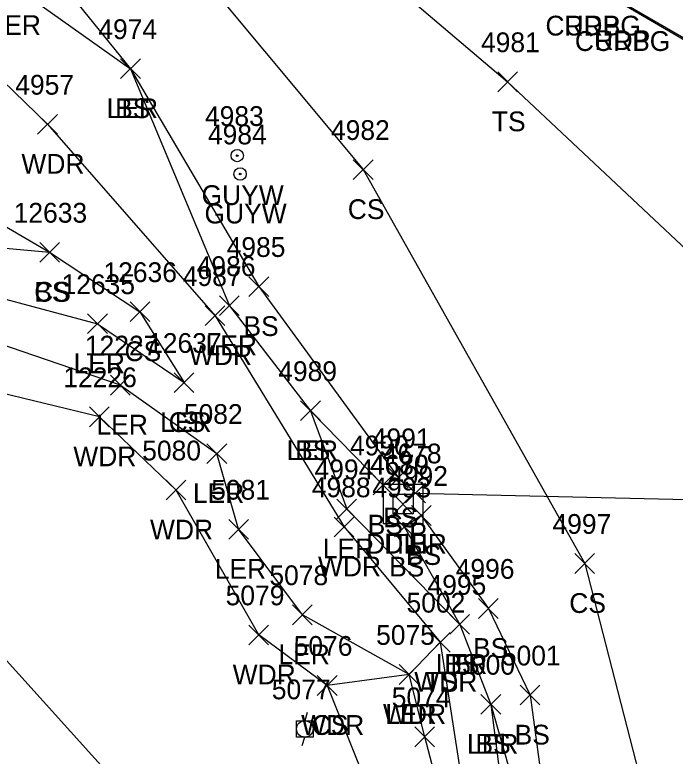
# Model space of a CAD drawing. Extents: x 1462089 to 1464015, y 730534 to 736144.
# Drawn here: x 1462520.7 to 1462587.6, y 731574.8 to 731649.8 of the extents above; entities that cross this region are included whole.
import ezdxf

# ---------------------------------------------------------------- set-up
doc = ezdxf.new("R2010")
doc.units = 0
for name, color, linetype in [('D_A', 7, 'Continuous'), ('D_I', 7, 'Continuous'), ('D_TIC', 7, 'Continuous'), ('DCP', 7, 'Continuous'), ('DS', 7, 'Continuous'), ('L_A', 7, 'Continuous'), ('L_I', 7, 'Continuous'), ('L_TIC', 7, 'Continuous'), ('LARO', 7, 'Continuous'), ('LAWA', 7, 'Continuous'), ('LELB', 7, 'Continuous'), ('P_A', 7, 'Continuous'), ('PET', 7, 'Continuous'), ('R_A', 7, 'Continuous'), ('RC', 7, 'Continuous'), ('U_A', 7, 'Continuous'), ('U_I', 7, 'Continuous'), ('UP', 7, 'Continuous'), ('UPGW', 7, 'Continuous')]:
    doc.layers.add(name, color=color, linetype=linetype)

msp = doc.modelspace()

# ---------------------------------------------------------------- linework, layer by layer
at = {"layer": 'D_TIC'}
for points in [[(1462560.299, 731600.383), (1462562.299, 731602.383)], [(1462562.299, 731600.383), (1462560.299, 731602.383)], [(1462559.037, 731599.257), (1462561.037, 731601.257)], [(1462561.037, 731599.257), (1462559.037, 731601.257)]]:
    msp.add_lwpolyline(points, dxfattribs=at)
at = {"layer": 'DCP'}
msp.add_lwpolyline([(1462561.299, 731601.383), (1462626.385, 731599.866)], dxfattribs=at)
at = {"layer": 'DS'}
for p, q in [((1462558.056, 731602.265), (1462562.056, 731602.265)), ((1462558.056, 731598.265), (1462558.067, 731602.265)), ((1462562.056, 731602.265), (1462562.056, 731598.265)), ((1462559.056, 731601.265), (1462561.056, 731601.265)), ((1462559.056, 731599.265), (1462559.056, 731601.265)), ((1462561.056, 731601.265), (1462561.056, 731599.265)), ((1462560.059, 731600.275), (1462560.059, 731600.275)), ((1462561.056, 731599.265), (1462559.056, 731599.265)), ((1462562.056, 731598.265), (1462558.056, 731598.265)), ((1462560.556, 731598.265), (1462561.056, 731598.265))]:
    msp.add_line(p, q, dxfattribs=at)
at = {"layer": 'L_TIC'}
for points in [[(1462531.459, 731643.31), (1462533.459, 731645.31)], [(1462533.459, 731643.31), (1462531.459, 731645.31)], [(1462531.459, 731643.31), (1462533.459, 731645.31)], [(1462533.459, 731643.31), (1462531.459, 731645.31)], [(1462569.627, 731641.981), (1462571.627, 731643.981)], [(1462571.627, 731641.981), (1462569.627, 731643.981)], [(1462523.054, 731637.685), (1462525.054, 731639.685)], [(1462525.054, 731637.685), (1462523.054, 731639.685)], [(1462555.009, 731633.101), (1462557.009, 731635.101)], [(1462557.009, 731633.101), (1462555.009, 731635.101)], [(1462523.269, 731624.736), (1462525.269, 731626.736)], [(1462525.269, 731624.736), (1462523.269, 731626.736)], [(1462523.269, 731624.736), (1462525.269, 731626.736)], [(1462525.269, 731624.736), (1462523.269, 731626.736)], [(1462544.45, 731621.268), (1462546.45, 731623.268)], [(1462546.45, 731621.268), (1462544.45, 731623.268)], [(1462541.472, 731619.329), (1462543.472, 731621.329)], [(1462543.472, 731619.329), (1462541.472, 731621.329)], [(1462532.413, 731618.725), (1462534.413, 731620.725)], [(1462534.413, 731618.725), (1462532.413, 731620.725)], [(1462540.013, 731618.326), (1462542.013, 731620.326)], [(1462542.013, 731618.326), (1462540.013, 731620.326)], [(1462528.113, 731617.507), (1462530.113, 731619.507)], [(1462530.113, 731617.507), (1462528.113, 731619.507)], [(1462530.429, 731611.297), (1462532.429, 731613.297)], [(1462532.429, 731611.297), (1462530.429, 731613.297)], [(1462536.875, 731611.559), (1462538.875, 731613.559)], [(1462538.875, 731611.559), (1462536.875, 731613.559)], [(1462536.875, 731611.559), (1462538.875, 731613.559)], [(1462538.875, 731611.559), (1462536.875, 731613.559)], [(1462549.678, 731608.71), (1462551.678, 731610.71)], [(1462551.678, 731608.71), (1462549.678, 731610.71)], [(1462549.678, 731608.71), (1462551.678, 731610.71)], [(1462551.678, 731608.71), (1462549.678, 731610.71)], [(1462528.306, 731608.09), (1462530.306, 731610.09)], [(1462530.306, 731608.09), (1462528.306, 731610.09)], [(1462540.194, 731604.376), (1462542.194, 731606.376)], [(1462542.194, 731604.376), (1462540.194, 731606.376)], [(1462558.575, 731601.916), (1462560.575, 731603.916)], [(1462560.575, 731601.916), (1462558.575, 731603.916)], [(1462558.575, 731601.916), (1462560.575, 731603.916)], [(1462560.575, 731601.916), (1462558.575, 731603.916)], [(1462557.02, 731601.19), (1462559.02, 731603.19)], [(1462559.02, 731601.19), (1462557.02, 731603.19)], [(1462536.068, 731600.683), (1462538.068, 731602.683)], [(1462538.068, 731600.683), (1462536.068, 731602.683)], [(1462553.342, 731598.778), (1462555.342, 731600.778)], [(1462555.342, 731598.778), (1462553.342, 731600.778)], [(1462560.893, 731598.11), (1462562.893, 731600.11)], [(1462562.893, 731598.11), (1462560.893, 731600.11)], [(1462560.893, 731598.11), (1462562.893, 731600.11)], [(1462562.893, 731598.11), (1462560.893, 731600.11)], [(1462542.397, 731596.715), (1462544.397, 731598.715)], [(1462544.397, 731596.715), (1462542.397, 731598.715)], [(1462553.07, 731596.956), (1462555.07, 731598.956)], [(1462555.07, 731596.956), (1462553.07, 731598.956)], [(1462559.194, 731596.941), (1462561.194, 731598.941)], [(1462561.194, 731596.941), (1462559.194, 731598.941)], [(1462577.427, 731593.254), (1462579.427, 731595.254)], [(1462579.427, 731593.254), (1462577.427, 731595.254)], [(1462548.852, 731588.064), (1462550.852, 731590.064)], [(1462550.852, 731588.064), (1462548.852, 731590.064)], [(1462567.687, 731588.707), (1462569.687, 731590.707)], [(1462569.687, 731588.707), (1462567.687, 731590.707)], [(1462564.778, 731587.089), (1462566.778, 731589.089)], [(1462566.778, 731587.089), (1462564.778, 731589.089)], [(1462564.778, 731587.089), (1462566.778, 731589.089)], [(1462566.778, 731587.089), (1462564.778, 731589.089)], [(1462544.438, 731586.026), (1462546.438, 731588.026)], [(1462546.438, 731586.026), (1462544.438, 731588.026)], [(1462562.813, 731585.287), (1462564.813, 731587.287)], [(1462564.813, 731585.287), (1462562.813, 731587.287)], [(1462562.813, 731585.287), (1462564.813, 731587.287)], [(1462564.813, 731585.287), (1462562.813, 731587.287)], [(1462559.655, 731582.026), (1462561.655, 731584.026)], [(1462561.655, 731582.026), (1462559.655, 731584.026)], [(1462559.655, 731582.026), (1462561.655, 731584.026)], [(1462561.655, 731582.026), (1462559.655, 731584.026)], [(1462551.367, 731580.915), (1462553.367, 731582.915)], [(1462553.367, 731580.915), (1462551.367, 731582.915)], [(1462551.367, 731580.915), (1462553.367, 731582.915)], [(1462553.367, 731580.915), (1462551.367, 731582.915)], [(1462571.894, 731579.941), (1462573.894, 731581.941)], [(1462573.894, 731579.941), (1462571.894, 731581.941)], [(1462567.931, 731579.005), (1462569.931, 731581.005)], [(1462569.931, 731579.005), (1462567.931, 731581.005)], [(1462567.931, 731579.005), (1462569.931, 731581.005)], [(1462569.931, 731579.005), (1462567.931, 731581.005)], [(1462561.237, 731575.714), (1462563.237, 731577.714)], [(1462563.237, 731575.714), (1462561.237, 731577.714)]]:
    msp.add_lwpolyline(points, dxfattribs=at)
at = {"layer": 'LARO'}
for points in [[(1462346.484, 731772.245), (1462377.204, 731754.639), (1462387.4, 731743.258), (1462405.336, 731739.989), (1462422.595, 731728.101), (1462430.525, 731721.568), (1462436.62, 731722.191), (1462456.917, 731710.315), (1462466.227, 731695.84), (1462493.617, 731678.674), (1462505.155, 731669.137), (1462520.606, 731652.722), (1462532.459, 731644.31), (1462542.472, 731620.329), (1462550.678, 731609.71), (1462554.342, 731599.778), (1462565.778, 731588.089), (1462568.931, 731580.005), (1462570.713, 731566.112), (1462578.995, 731548.691), (1462583.025, 731541.222), (1462579.132, 731509.105)], [(1462531.429, 731612.297), (1462506.669, 731620.754), (1462488.794, 731629.315), (1462466.858, 731635.352), (1462444.766, 731644.234), (1462441.056, 731648.619), (1462444.441, 731652.191), (1462428.639, 731671.832), (1462423.479, 731679.306)], [(1462509.927, 731627.255), (1462515.984, 731622.019), (1462529.113, 731618.507), (1462537.875, 731612.559)], [(1462531.429, 731612.297), (1462541.194, 731605.376)], [(1462573.728, 731494.742), (1462573.697, 731512.314), (1462577.788, 731520.965), (1462576.572, 731538.535), (1462568.613, 731559.706), (1462565.96, 731562.601), (1462562.237, 731576.714), (1462560.655, 731583.026), (1462549.852, 731589.064), (1462543.397, 731597.715), (1462541.194, 731605.376)]]:
    msp.add_lwpolyline(points, dxfattribs=at)
at = {"layer": 'LAWA'}
for points in [[(1462353.486, 731759.008), (1462368.091, 731753.052), (1462369.061, 731740.918), (1462384.402, 731732.963), (1462402.803, 731736.533), (1462419.775, 731723.669), (1462429.629, 731717.395), (1462437.688, 731715.11), (1462449.892, 731706.469), (1462461.801, 731688.892), (1462471.295, 731683.685), (1462488.007, 731676.157), (1462499.088, 731668.041), (1462511.531, 731650.799), (1462524.054, 731638.685), (1462541.013, 731619.326), (1462554.07, 731597.956), (1462563.813, 731586.287), (1462560.655, 731583.026), (1462552.367, 731581.915), (1462545.438, 731587.026), (1462537.068, 731601.683)], [(1462529.306, 731609.09), (1462503.687, 731615.303), (1462482.961, 731621.756), (1462463.284, 731631.864), (1462443.061, 731640.907), (1462419.395, 731655.593), (1462381.114, 731680.146), (1462355.304, 731693.116), (1462311.252, 731715.6), (1462266.509, 731744.615)], [(1462529.306, 731609.09), (1462537.068, 731601.683)]]:
    msp.add_lwpolyline(points, dxfattribs=at)
at = {"layer": 'LELB'}
for points in [[(1462199.973, 731862.797), (1462226.522, 731848.633), (1462244.469, 731839.44), (1462279.961, 731820.277), (1462307.49, 731805.659), (1462330.44, 731793.577), (1462345.388, 731783.622), (1462390.349, 731759.437), (1462428.457, 731739.343), (1462460.592, 731719.83), (1462475.515, 731708.509), (1462501.897, 731689.799), (1462542.27, 731667.043), (1462570.627, 731642.981), (1462603.035, 731612.581), (1462606.866, 731588.462), (1462599.353, 731546.54), (1462591.287, 731500.049)], [(1462501.897, 731689.799), (1462536.038, 731658.093), (1462556.009, 731634.101), (1462578.427, 731594.254), (1462586.04, 731564.762), (1462589.678, 731543.502), (1462586.226, 731501.088), (1462585.38, 731483.091)], [(1462507.864, 731671.1), (1462523.961, 731654.827), (1462532.459, 731644.31), (1462545.45, 731622.268), (1462559.575, 731602.916)], [(1462482.103, 731646.041), (1462492.873, 731646.898), (1462507.297, 731640.119), (1462513.55, 731631.987), (1462524.269, 731625.736), (1462533.413, 731619.725), (1462537.875, 731612.559)], [(1462513.55, 731631.987), (1462514.974, 731626.603), (1462524.269, 731625.736)], [(1462485.976, 731369.759), (1462496.617, 731406.25), (1462504.749, 731449.66), (1462520.791, 731495.659), (1462536.556, 731542.788), (1462536.235, 731566.321), (1462513.747, 731591.256), (1462486.764, 731604.845), (1462473.899, 731602.315), (1462450.444, 731613.383), (1462450.102, 731624.659)], [(1462550.678, 731609.71), (1462558.02, 731602.19), (1462559.575, 731602.916)], [(1462561.893, 731599.11), (1462560.194, 731597.941), (1462565.778, 731588.089)], [(1462561.893, 731599.11), (1462568.687, 731589.707), (1462572.894, 731580.941), (1462574.892, 731566.204), (1462582.199, 731549.938), (1462584.642, 731541.473), (1462582.439, 731502.238), (1462581.625, 731485.919)], [(1462563.813, 731586.287), (1462567.019, 731565.613), (1462565.96, 731562.601), (1462564.718, 731551.054), (1462571.579, 731530.336), (1462567.567, 731501.933), (1462566.111, 731482.199), (1462562.411, 731454.244), (1462553.122, 731413.381), (1462540.13, 731378.267), (1462533.588, 731363.392), (1462525.417, 731358.784)], [(1462552.367, 731581.915), (1462564.718, 731551.054)], [(1462568.931, 731580.005), (1462573.043, 731565.54), (1462578.995, 731548.691)]]:
    msp.add_lwpolyline(points, dxfattribs=at)
at = {"layer": 'PET'}
msp.add_lwpolyline([(1462201.656, 731866.043), (1462245.703, 731842.087), (1462281.75, 731822.984), (1462308.734, 731808.187), (1462347.652, 731787.037), (1462392.209, 731761.837), (1462429.222, 731740.598), (1462448.896, 731730.041), (1462477.729, 731709.286), (1462504.154, 731693.872), (1462543.73, 731671.863), (1462578.876, 731652.667), (1462581.934, 731651.196), (1462611.072, 731634.393), (1462616.428, 731629.037), (1462620.383, 731622.699), (1462623.597, 731614.859), (1462625.47, 731606.659), (1462626.295, 731597.635), (1462624.657, 731584.618)], dxfattribs=at)
at = {"layer": 'RC'}
msp.add_lwpolyline([(1462578.876, 731652.667), (1462581.853, 731651.105), (1462610.886, 731634.194), (1462616.077, 731628.889), (1462620.047, 731622.437), (1462623.426, 731614.745), (1462625.292, 731606.639), (1462626.134, 731597.744), (1462624.33, 731584.747), (1462611.563, 731543.975), (1462595.819, 731494.509), (1462581.283, 731447.508), (1462570.058, 731410.565), (1462558.535, 731373.066), (1462554.642, 731364.371), (1462548.372, 731356.851), (1462540.364, 731351.769), (1462530.201, 731348.551)], dxfattribs=at)
at = {"layer": 'UP'}
for p, q in [((1462550.346, 731579.186), (1462550.096, 731578.353)), ((1462549.263, 731576.686), (1462549.263, 731578.353)), ((1462549.263, 731578.353), (1462550.93, 731578.353)), ((1462550.93, 731578.353), (1462550.93, 731576.686)), ((1462550.096, 731577.519), (1462550.096, 731577.519)), ((1462550.93, 731576.686), (1462549.263, 731576.686)), ((1462549.846, 731575.853), (1462550.096, 731576.686))]:
    msp.add_line(p, q, dxfattribs=at)
msp.add_circle((1462550.096, 731577.519), 0.833, dxfattribs=at)
at = {"layer": 'UPGW'}
for centre, radius in [((1462543.256, 731635.518), 0.625), ((1462543.256, 731635.518), 0.0833), ((1462543.554, 731633.656), 0.625), ((1462543.554, 731633.656), 0.0833)]:
    msp.add_circle(centre, radius, dxfattribs=at)

# ---------------------------------------------------------------- texts
at = {"layer": 'D_A'}
for s, p in [('P', (1462560.677, 731596.383)), ('DITHR', (1462556.303, 731595.244)), ('DIB', (1462558.139, 731595.257))]:
    msp.add_text(s, height=2, dxfattribs=at).set_placement(p)
at = {"layer": 'D_I'}
for s, p in [('4678', (1462557.992, 731604.383)), ('4680', (1462556.681, 731603.244)), ('4679', (1462556.722, 731603.257))]:
    msp.add_text(s, height=2, dxfattribs=at).set_placement(p)
at = {"layer": 'L_A'}
for s, p in [('LER', (1462518.189, 731647.722)), ('LER', (1462530.042, 731639.31)), ('BS', (1462530.9, 731639.31)), ('TS', (1462569.036, 731637.981)), ('WDR', (1462521.416, 731633.685)), ('CS', (1462554.45, 731629.101)), ('CS', (1462522.71, 731620.736)), ('BS', (1462522.71, 731620.736)), ('BS', (1462543.891, 731617.268)), ('LER', (1462540.055, 731615.329)), ('CS', (1462531.854, 731614.725)), ('WDR', (1462538.375, 731614.326)), ('LER', (1462526.696, 731613.507)), ('LER', (1462535.458, 731607.559)), ('CS', (1462536.316, 731607.559)), ('LER', (1462529.012, 731607.297)), ('LER', (1462548.261, 731604.71)), ('BS', (1462549.119, 731604.71)), ('WDR', (1462526.668, 731604.09)), ('LER', (1462538.777, 731600.376)), ('BS', (1462558.016, 731597.916)), ('BS', (1462558.016, 731597.916)), ('BS', (1462556.461, 731597.19)), ('WDR', (1462534.431, 731596.683)), ('LER', (1462551.924, 731594.778)), ('BS', (1462560.334, 731594.11)), ('BS', (1462560.334, 731594.11)), ('LER', (1462540.98, 731592.715)), ('WDR', (1462551.432, 731592.956)), ('BS', (1462558.635, 731592.941)), ('CS', (1462576.868, 731589.254)), ('BS', (1462567.128, 731584.707)), ('LER', (1462547.435, 731584.064)), ('LER', (1462563.361, 731583.089)), ('BS', (1462564.219, 731583.089)), ('WDR', (1462542.8, 731582.026)), ('WDR', (1462561.175, 731581.287)), ('TS', (1462562.222, 731581.287)), ('WDR', (1462558.017, 731578.026)), ('LER', (1462558.237, 731578.026)), ('WDR', (1462549.73, 731576.915)), ('CS', (1462550.808, 731576.915)), ('BS', (1462571.335, 731575.941)), ('LER', (1462566.513, 731575.005)), ('BS', (1462567.372, 731575.005))]:
    msp.add_text(s, height=2, dxfattribs=at).set_placement(p)
at = {"layer": 'L_I'}
for s, p in [('4974', (1462529.2, 731647.31)), ('4974', (1462529.2, 731647.31)), ('4981', (1462567.934, 731645.981)), ('4957', (1462520.794, 731641.685)), ('4982', (1462552.749, 731637.101)), ('12633', (1462520.631, 731628.736)), ('12633', (1462520.631, 731628.736)), ('4985', (1462542.19, 731625.268)), ('4986', (1462539.158, 731623.329)), ('12636', (1462529.72, 731622.725)), ('4987', (1462537.753, 731622.326)), ('12635', (1462525.476, 731621.507)), ('12227', (1462527.839, 731615.297)), ('12637', (1462534.238, 731615.559)), ('12637', (1462534.238, 731615.559)), ('12226', (1462525.66, 731612.09)), ('4989', (1462547.411, 731612.71)), ('4989', (1462547.411, 731612.71)), ('5082', (1462537.856, 731608.376)), ('4991', (1462556.882, 731605.916)), ('4991', (1462556.882, 731605.916)), ('5080', (1462533.643, 731604.683)), ('4990', (1462554.674, 731605.19)), ('4994', (1462551.082, 731602.778)), ('4992', (1462558.634, 731602.11)), ('4992', (1462558.634, 731602.11)), ('4988', (1462550.81, 731600.956)), ('4993', (1462556.935, 731600.941)), ('5081', (1462540.626, 731600.715)), ('4997', (1462575.168, 731597.254)), ('4996', (1462565.372, 731592.707)), ('5078', (1462546.514, 731592.064)), ('4995', (1462562.519, 731591.089)), ('4995', (1462562.519, 731591.089)), ('5079', (1462542.091, 731590.026)), ('5002', (1462560.396, 731589.287)), ('5002', (1462560.396, 731589.287)), ('5075', (1462557.316, 731586.026)), ('5075', (1462557.316, 731586.026)), ('5076', (1462548.974, 731584.915)), ('5076', (1462548.974, 731584.915)), ('5001', (1462570.044, 731583.941)), ('5000', (1462565.427, 731583.005)), ('5000', (1462565.427, 731583.005)), ('5074', (1462558.898, 731579.714))]:
    msp.add_text(s, height=2, dxfattribs=at).set_placement(p)
at = {"layer": 'P_A'}
for p in [(1462576.364, 731647.667), (1462579.422, 731646.196)]:
    msp.add_text('RDP', height=2, dxfattribs=at).set_placement(p)
at = {"layer": 'R_A'}
for p in [(1462574.458, 731647.667), (1462577.435, 731646.105)]:
    msp.add_text('CURBG', height=2, dxfattribs=at).set_placement(p)
at = {"layer": 'U_A'}
for p in [(1462539.65, 731630.518), (1462539.947, 731628.656)]:
    msp.add_text('GUYW', height=2, dxfattribs=at).set_placement(p)
at = {"layer": 'U_I'}
for s, p in [('4983', (1462539.996, 731638.518)), ('4984', (1462540.294, 731636.656)), ('5077', (1462546.758, 731580.519))]:
    msp.add_text(s, height=2, dxfattribs=at).set_placement(p)

doc.saveas('drawing.dxf')
